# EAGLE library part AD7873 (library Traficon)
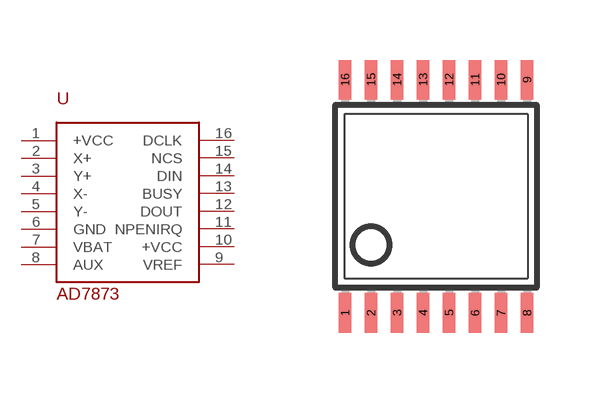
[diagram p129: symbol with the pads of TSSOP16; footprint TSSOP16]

Designator prefix U

## AD7873  [TSSOP16]
1  +VCC
2  X+
3  Y+
4  X-
5  Y-
6  GND
7  VBAT
8  AUX
9  VREF
10  +VCC
11  NPENIRQ
12  DOUT
13  BUSY
14  DIN
15  NCS
16  DCLK

## Footprint TSSOP16 (pad centres in mm)
Thin Shrink Small Outline Plastic 16 http://www.maxim-ic.com .. MAX3223-MAX3243.pdf
smd 0.305 x 0.991: 1 -2.275,-2.918; 2 -1.625,-2.918; 3 -0.975,-2.918; 4 -0.325,-2.918; 5 0.325,-2.918; 6 0.975,-2.918; 7 1.625,-2.918; 8 2.275,-2.918; 9 2.275,2.918; 10 1.625,2.918; 11 0.975,2.918; 12 0.325,2.918; 13 -0.325,2.918; 14 -0.975,2.918; 15 -1.625,2.918; 16 -2.275,2.918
